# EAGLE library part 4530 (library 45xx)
Dual 5-input MAJORITY GATE
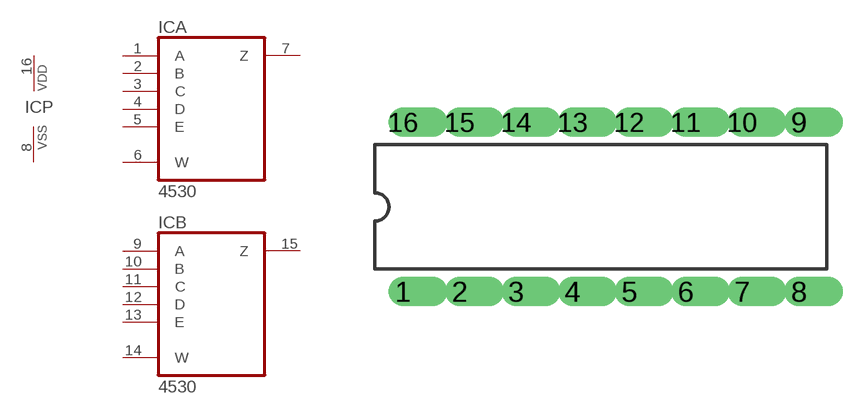
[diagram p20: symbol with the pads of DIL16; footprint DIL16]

Designator prefix IC; gates A=4530 B=4530 P=PWRN

## 4530N  [DIL16]
1  A:A  in
2  A:B  in
3  A:C  in
4  A:D  in
5  A:E  in
6  A:W  in
7  A:Z  out
8  P:VSS  pwr
9  B:A  in
10  B:B  in
11  B:C  in
12  B:D  in
13  B:E  in
14  B:W  in
15  B:Z  out
16  P:VDD  pwr

## Footprint DIL16 (pad centres in mm)
Dual In Line
drill 0.813 offset: 1 -8.89,-3.81; 2 -6.35,-3.81; 3 -3.81,-3.81; 4 -1.27,-3.81; 5 1.27,-3.81; 6 3.81,-3.81; 7 6.35,-3.81; 8 8.89,-3.81; 9 8.89,3.81; 10 6.35,3.81; 11 3.81,3.81; 12 1.27,3.81; 13 -1.27,3.81; 14 -3.81,3.81; 15 -6.35,3.81; 16 -8.89,3.81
